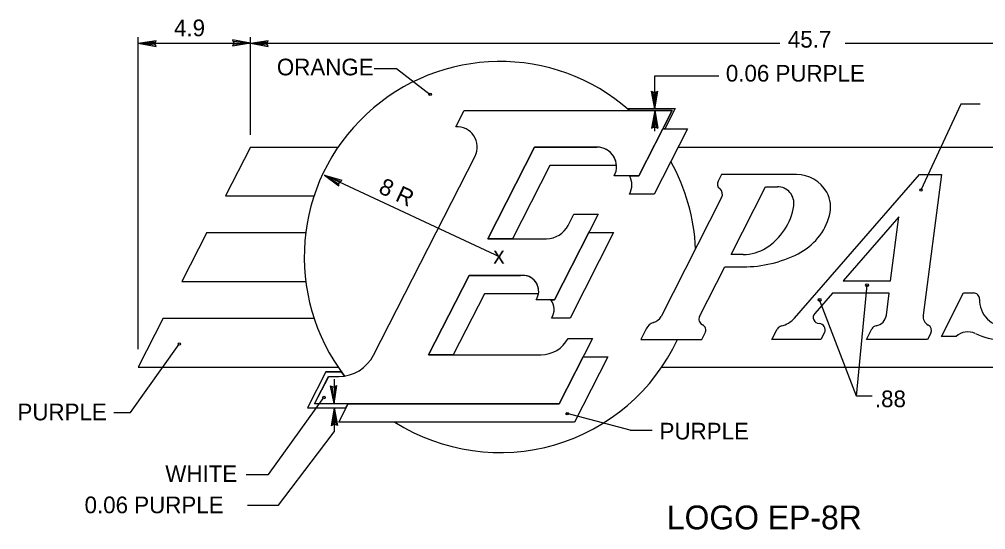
# Model space of a CAD drawing. Extents: x 10268197 to 10269179, y 2141503 to 2142677.
# Drawn here: x 10268587.94 to 10268622.88, y 2142117.46 to 2142135.93 of the extents above; entities that cross this region are included whole.
import ezdxf

# ---------------------------------------------------------------- set-up
doc = ezdxf.new("R2010")
doc.units = 0
for name, color, linetype in [('1', 7, 'Continuous'), ('Default', 7, 'Continuous'), ('TextDetails', 7, 'Continuous')]:
    doc.layers.add(name, color=color, linetype=linetype)

msp = doc.modelspace()

# ---------------------------------------------------------------- linework, layer by layer
at = {"layer": '1'}
for p, q in [((10268592.239, 2142123.995), (10268592.239, 2142135.291)), ((10268592.239, 2142135.07), (10268615.441, 2142135.07)), ((10268596.293, 2142131.752), (10268596.293, 2142135.291)), ((10268617.796, 2142135.07), (10268636.996, 2142135.07)), ((10268600.771, 2142134.159), (10268601.571, 2142134.159)), ((10268601.571, 2142134.159), (10268602.792, 2142133.217)), ((10268610.92, 2142133.893), (10268613.227, 2142133.893)), ((10268610.92, 2142132.722), (10268610.92, 2142133.893)), ((10268610.92, 2142131.88), (10268610.92, 2142132.642)), ((10268621.981, 2142132.861), (10268620.541, 2142129.754)), ((10268622.684, 2142132.861), (10268621.981, 2142132.861)), ((10268605.319, 2142127.328), (10268598.966, 2142130.29)), ((10268618.205, 2142122.289), (10268618.591, 2142126.308)), ((10268618.205, 2142122.289), (10268616.876, 2142125.778)), ((10268591.961, 2142121.699), (10268593.719, 2142124.177)), ((10268599.318, 2142122.905), (10268599.318, 2142122.025)), ((10268596.943, 2142119.455), (10268598.95, 2142122.244)), ((10268618.777, 2142122.289), (10268618.205, 2142122.289)), ((10268599.318, 2142121.868), (10268599.318, 2142120.996)), ((10268591.348, 2142121.699), (10268591.961, 2142121.699)), ((10268610.021, 2142121.063), (10268607.749, 2142121.658)), ((10268598.717, 2142120.203), (10268599.318, 2142120.996)), ((10268610.021, 2142121.063), (10268610.822, 2142121.063)), ((10268597.313, 2142118.35), (10268598.717, 2142120.203)), ((10268596.142, 2142119.455), (10268596.943, 2142119.455)), ((10268596.189, 2142118.35), (10268597.313, 2142118.35))]:
    msp.add_line(p, q, dxfattribs=at)
for centre, radius in [((10268602.792, 2142133.216), 0.0442), ((10268620.541, 2142129.753), 0.0442), ((10268618.591, 2142126.308), 0.0518), ((10268616.876, 2142125.778), 0.0518), ((10268593.719, 2142124.177), 0.0442), ((10268598.95, 2142122.243), 0.0442), ((10268607.749, 2142121.657), 0.0442)]:
    msp.add_circle(centre, radius, dxfattribs=at)
at = {"layer": 'Default'}
for p, q in [((10268592.239, 2142135.07), (10268592.886, 2142135.173)), ((10268592.239, 2142135.07), (10268592.859, 2142135.113)), ((10268592.239, 2142135.07), (10268592.882, 2142134.945)), ((10268592.239, 2142135.07), (10268592.857, 2142135.005)), ((10268592.834, 2142135.06), (10268592.886, 2142135.173)), ((10268592.882, 2142134.945), (10268592.834, 2142135.06)), ((10268595.697, 2142135.08), (10268595.646, 2142134.967)), ((10268596.293, 2142135.07), (10268595.646, 2142134.967)), ((10268596.293, 2142135.07), (10268595.65, 2142135.195)), ((10268595.65, 2142135.195), (10268595.697, 2142135.08)), ((10268596.293, 2142135.07), (10268595.674, 2142135.027)), ((10268596.293, 2142135.07), (10268595.675, 2142135.135)), ((10268596.293, 2142135.07), (10268596.94, 2142135.173)), ((10268596.293, 2142135.07), (10268596.912, 2142135.113)), ((10268596.293, 2142135.07), (10268596.936, 2142134.945)), ((10268596.293, 2142135.07), (10268596.911, 2142135.005)), ((10268596.888, 2142135.06), (10268596.94, 2142135.173)), ((10268596.936, 2142134.945), (10268596.888, 2142135.06)), ((10268610.921, 2142132.691), (10268610.796, 2142133.334)), ((10268610.796, 2142133.334), (10268610.911, 2142133.287)), ((10268610.921, 2142132.691), (10268610.856, 2142133.309)), ((10268610.911, 2142133.287), (10268611.024, 2142133.338)), ((10268610.921, 2142132.691), (10268611.024, 2142133.338)), ((10268610.921, 2142132.691), (10268610.965, 2142133.311)), ((10268603.718, 2142132.043), (10268604.019, 2142132.637)), ((10268604.019, 2142132.637), (10268611.54, 2142132.637)), ((10268609.924, 2142132.703), (10268611.649, 2142132.703)), ((10268611.54, 2142132.637), (10268610.336, 2142130.271)), ((10268610.921, 2142132.638), (10268610.796, 2142131.995)), ((10268610.921, 2142132.638), (10268610.856, 2142132.02)), ((10268610.921, 2142132.638), (10268611.024, 2142131.992)), ((10268610.921, 2142132.638), (10268610.965, 2142132.019)), ((10268611.649, 2142132.703), (10268611.277, 2142131.973)), ((10268610.334, 2142130.269), (10268611.203, 2142131.973)), ((10268610.334, 2142130.269), (10268611.203, 2142131.973)), ((10268610.796, 2142131.995), (10268610.911, 2142132.043)), ((10268612.097, 2142131.973), (10268610.891, 2142129.608)), ((10268612.097, 2142131.973), (10268610.891, 2142129.608)), ((10268610.911, 2142132.043), (10268611.024, 2142131.992)), ((10268611.203, 2142131.973), (10268612.097, 2142131.973)), ((10268611.203, 2142131.973), (10268612.097, 2142131.973)), ((10268596.293, 2142131.31), (10268595.392, 2142129.54)), ((10268596.293, 2142131.31), (10268599.466, 2142131.31)), ((10268606.568, 2142131.31), (10268604.878, 2142127.992)), ((10268604.878, 2142127.992), (10268606.568, 2142131.31)), ((10268604.878, 2142127.992), (10268606.568, 2142131.31)), ((10268608.823, 2142131.31), (10268606.568, 2142131.31)), ((10268606.568, 2142131.31), (10268608.823, 2142131.31)), ((10268606.568, 2142131.31), (10268608.823, 2142131.31)), ((10268611.758, 2142131.31), (10268636.996, 2142131.31)), ((10268600.745, 2142123.777), (10268604.417, 2142130.984)), ((10268607.124, 2142130.646), (10268605.771, 2142127.992)), ((10268607.124, 2142130.646), (10268605.771, 2142127.992)), ((10268609.531, 2142130.646), (10268607.124, 2142130.646)), ((10268609.531, 2142130.646), (10268607.124, 2142130.646)), ((10268598.966, 2142130.29), (10268599.595, 2142130.11)), ((10268598.966, 2142130.29), (10268599.496, 2142129.906)), ((10268598.966, 2142130.29), (10268599.498, 2142129.97)), ((10268598.966, 2142130.29), (10268599.545, 2142130.068)), ((10268610.336, 2142130.271), (10268609.45, 2142130.271)), ((10268610.005, 2142130.269), (10268610.334, 2142130.269)), ((10268610.005, 2142130.269), (10268610.334, 2142130.269)), ((10268613.326, 2142130.314), (10268613.206, 2142130.078)), ((10268616.036, 2142130.314), (10268613.326, 2142130.314)), ((10268615.968, 2142125.118), (10268620.486, 2142130.314)), ((10268620.486, 2142130.314), (10268621.282, 2142130.314)), ((10268621.282, 2142130.314), (10268620.62, 2142125.223)), ((10268599.496, 2142129.906), (10268599.501, 2142130.029)), ((10268599.501, 2142130.029), (10268599.595, 2142130.11)), ((10268613.673, 2142127.416), (10268614.925, 2142129.871)), ((10268614.925, 2142129.871), (10268615.352, 2142129.871)), ((10268595.392, 2142129.54), (10268598.594, 2142129.54)), ((10268610.891, 2142129.608), (10268610.006, 2142129.608)), ((10268610.891, 2142129.608), (10268610.006, 2142129.608)), ((10268613.334, 2142129.478), (10268611.143, 2142125.179)), ((10268608.872, 2142128.876), (10268607.295, 2142125.779)), ((10268607.783, 2142128.474), (10268607.988, 2142128.876)), ((10268607.988, 2142128.876), (10268608.872, 2142128.876)), ((10268619.745, 2142128.788), (10268617.725, 2142126.465)), ((10268619.443, 2142126.465), (10268619.745, 2142128.788)), ((10268594.717, 2142128.213), (10268593.816, 2142126.443)), ((10268594.717, 2142128.213), (10268598.295, 2142128.213)), ((10268607.295, 2142125.779), (10268608.535, 2142128.213)), ((10268607.295, 2142125.779), (10268608.535, 2142128.213)), ((10268609.428, 2142128.213), (10268607.85, 2142125.116)), ((10268609.428, 2142128.213), (10268607.85, 2142125.116)), ((10268608.535, 2142128.213), (10268609.428, 2142128.213)), ((10268608.535, 2142128.213), (10268609.428, 2142128.213)), ((10268604.878, 2142127.992), (10268606.995, 2142127.992)), ((10268605.771, 2142127.992), (10268604.878, 2142127.992)), ((10268605.771, 2142127.992), (10268604.878, 2142127.992)), ((10268614.112, 2142127.416), (10268613.673, 2142127.416)), ((10268604.202, 2142126.664), (10268602.736, 2142123.788)), ((10268602.736, 2142123.788), (10268604.202, 2142126.664)), ((10268602.736, 2142123.788), (10268604.202, 2142126.664)), ((10268606.143, 2142126.664), (10268604.202, 2142126.664)), ((10268604.202, 2142126.664), (10268606.06, 2142126.658)), ((10268604.202, 2142126.664), (10268606.06, 2142126.658)), ((10268612.533, 2142125.179), (10268613.448, 2142126.974)), ((10268613.448, 2142126.974), (10268614.112, 2142126.974)), ((10268593.816, 2142126.443), (10268598.295, 2142126.443)), ((10268617.725, 2142126.465), (10268619.443, 2142126.465)), ((10268604.757, 2142125.999), (10268603.63, 2142123.788)), ((10268604.757, 2142125.999), (10268603.63, 2142123.788)), ((10268606.71, 2142125.993), (10268604.757, 2142125.999)), ((10268606.71, 2142125.993), (10268604.757, 2142125.999)), ((10268617.342, 2142126.022), (10268616.7, 2142125.285)), ((10268619.398, 2142126.022), (10268617.342, 2142126.022)), ((10268619.292, 2142125.223), (10268619.398, 2142126.022)), ((10268621.279, 2142124.452), (10268622.082, 2142126.029)), ((10268622.082, 2142126.029), (10268622.438, 2142126.029)), ((10268607.295, 2142125.779), (10268606.628, 2142125.779)), ((10268607.156, 2142125.779), (10268607.295, 2142125.779)), ((10268607.156, 2142125.779), (10268607.295, 2142125.779)), ((10268593.14, 2142125.116), (10268592.239, 2142123.346)), ((10268593.14, 2142125.116), (10268598.594, 2142125.116)), ((10268607.85, 2142125.116), (10268607.187, 2142125.116)), ((10268607.85, 2142125.116), (10268607.187, 2142125.116)), ((10268610.605, 2142124.732), (10268610.407, 2142124.341)), ((10268612.619, 2142124.341), (10268612.739, 2142124.578)), ((10268615.154, 2142124.341), (10268615.346, 2142124.72)), ((10268617.054, 2142124.597), (10268616.924, 2142124.341)), ((10268618.568, 2142124.341), (10268618.764, 2142124.725)), ((10268620.897, 2142124.569), (10268620.78, 2142124.341)), ((10268608.663, 2142124.384), (10268607.458, 2142122.019)), ((10268607.778, 2142124.384), (10268608.663, 2142124.384)), ((10268610.407, 2142124.341), (10268612.619, 2142124.341)), ((10268616.924, 2142124.341), (10268615.154, 2142124.341)), ((10268620.78, 2142124.341), (10268618.568, 2142124.341)), ((10268621.817, 2142124.452), (10268621.279, 2142124.452)), ((10268602.736, 2142123.788), (10268606.797, 2142123.788)), ((10268603.63, 2142123.788), (10268602.736, 2142123.788)), ((10268603.63, 2142123.788), (10268602.736, 2142123.788)), ((10268607.458, 2142122.019), (10268608.325, 2142123.72)), ((10268607.458, 2142122.019), (10268608.325, 2142123.72)), ((10268609.219, 2142123.72), (10268608.013, 2142121.355)), ((10268609.219, 2142123.72), (10268608.013, 2142121.355)), ((10268608.325, 2142123.72), (10268609.219, 2142123.72)), ((10268608.325, 2142123.72), (10268609.219, 2142123.72)), ((10268592.239, 2142123.346), (10268599.466, 2142123.346)), ((10268599.019, 2142123.177), (10268598.354, 2142121.868)), ((10268599.019, 2142123.177), (10268599.584, 2142123.177)), ((10268611.171, 2142123.346), (10268632.938, 2142123.346)), ((10268598.61, 2142122.019), (10268599.112, 2142123.004)), ((10268599.112, 2142123.004), (10268599.483, 2142123.004)), ((10268599.318, 2142122.025), (10268599.192, 2142122.668)), ((10268599.192, 2142122.668), (10268599.307, 2142122.621)), ((10268599.318, 2142122.025), (10268599.253, 2142122.643)), ((10268599.307, 2142122.621), (10268599.42, 2142122.672)), ((10268599.318, 2142122.025), (10268599.42, 2142122.672)), ((10268599.318, 2142122.025), (10268599.361, 2142122.645)), ((10268598.354, 2142121.868), (10268599.741, 2142121.868)), ((10268607.458, 2142122.019), (10268598.61, 2142122.019)), ((10268599.318, 2142121.868), (10268599.215, 2142121.221)), ((10268599.318, 2142121.868), (10268599.274, 2142121.249)), ((10268599.318, 2142121.868), (10268599.442, 2142121.225)), ((10268599.318, 2142121.868), (10268599.382, 2142121.249)), ((10268599.495, 2142121.355), (10268599.832, 2142122.019)), ((10268599.495, 2142121.355), (10268599.832, 2142122.019)), ((10268599.832, 2142122.019), (10268607.458, 2142122.019)), ((10268599.832, 2142122.019), (10268607.458, 2142122.019)), ((10268599.327, 2142121.273), (10268599.215, 2142121.221)), ((10268599.442, 2142121.225), (10268599.327, 2142121.273)), ((10268608.013, 2142121.355), (10268599.495, 2142121.355)), ((10268608.013, 2142121.355), (10268599.495, 2142121.355))]:
    msp.add_line(p, q, dxfattribs=at)
for points in [[(10268609.924, 2142132.703), (10268611.649, 2142132.703), (10268611.277, 2142131.973), (10268611.203, 2142131.973), (10268611.54, 2142132.637), (10268610, 2142132.636)], [(10268599.584, 2142123.177), (10268599.019, 2142123.177), (10268598.354, 2142121.868), (10268599.741, 2142121.868), (10268599.832, 2142122.019), (10268598.61, 2142122.019), (10268599.125, 2142123.004), (10268599.488, 2142123.004), (10268599.7, 2142123.02)]]:
    msp.add_lwpolyline(points, close=True, dxfattribs=at)
for centre, radius, start, end in [((10268605.318, 2142127.327), 7.079, 48.5904, 217.4727), ((10268603.766, 2142131.315), 0.73, 332.9998, 93.8045), ((10268608.824, 2142130.601), 0.708, 332.2089, 90), ((10268608.824, 2142130.601), 0.708, 3.5833, 90), ((10268608.824, 2142130.601), 0.708, 3.5833, 90), ((10268605.318, 2142127.327), 7.079, 2.4236, 29.2771), ((10268609.379, 2142129.937), 0.708, 332.2089, 27.9127), ((10268609.379, 2142129.937), 0.708, 332.2089, 27.9127), ((10268616.036, 2142129.052), 1.261, 29.4315, 90), ((10268613.402, 2142129.977), 0.221, 152.9784, 231.1602), ((10268615.351, 2142129.274), 0.597, 351.076, 90), ((10268613.097, 2142129.598), 0.265, 333.0027, 51.1602), ((10268616.17, 2142129.128), 1.106, 344.7074, 29.4315), ((10268613.756, 2142129.524), 2.212, 302.4206, 351.076), ((10268615.104, 2142129.42), 2.212, 296.6431, 344.7074), ((10268606.994, 2142128.876), 0.885, 270, 332.9883), ((10268614.112, 2142128.964), 1.548, 270, 302.4206), ((10268614.112, 2142131.397), 4.424, 270, 296.6431), ((10268606.143, 2142126.088), 0.575, 350.3502, 98.3344), ((10268606.143, 2142126.088), 0.575, 350.3502, 98.3344), ((10268606.143, 2142126.088), 0.575, 327.421, 90), ((10268622.438, 2142125.807), 0.221, 358.6664, 90), ((10268606.702, 2142125.425), 0.575, 327.421, 37.9799), ((10268606.702, 2142125.425), 0.575, 327.421, 37.9799), ((10268623.654, 2142125.779), 0.995, 178.6665, 270), ((10268616.867, 2142125.139), 0.221, 138.9824, 268.6869), ((10268610.999, 2142124.53), 0.442, 106.4317, 152.9742), ((10268610.749, 2142125.379), 0.442, 286.4317, 332.9959), ((10268612.73, 2142125.078), 0.221, 152.9884, 244.7832), ((10268615.3, 2142125.698), 0.885, 282.7162, 318.9966), ((10268616.857, 2142124.697), 0.221, 332.9784, 88.6869), ((10268618.854, 2142125.279), 0.442, 279.2397, 352.5632), ((10268620.971, 2142125.176), 0.354, 172.5884, 241.8673), ((10268612.542, 2142124.677), 0.221, 333.0239, 64.7832), ((10268615.544, 2142124.619), 0.221, 102.7162, 153.0239), ((10268618.961, 2142124.624), 0.221, 99.2397, 153.0239), ((10268620.699, 2142124.669), 0.221, 332.9784, 61.8673), ((10268622.24, 2142124), 0.619, 64.3795, 133.1892), ((10268605.318, 2142127.327), 7.079, 237.5383, 335.047), ((10268606.797, 2142124.894), 1.106, 270, 332.5096), ((10268623.465, 2142126.553), 2.212, 244.3795, 270), ((10268599.483, 2142124.419), 1.416, 270, 332.9991)]:
    msp.add_arc(centre, radius, start, end, dxfattribs=at)

# ---------------------------------------------------------------- texts
at = {"layer": '1'}
for s, height, p in [('4.9', 0.6037, (10268593.53, 2142135.322)), ('45.7', 0.6037, (10268615.728, 2142134.909)), ('ORANGE', 0.6037, (10268597.249, 2142133.905)), ('0.06 PURPLE', 0.60368, (10268613.487, 2142133.679)), ('x', 0.604, (10268605.078, 2142127.092)), ('.88', 0.6037, (10268618.876, 2142121.892)), ('PURPLE', 0.6037, (10268587.869, 2142121.416)), ('PURPLE', 0.6037, (10268611.089, 2142120.722)), ('WHITE', 0.6037, (10268593.214, 2142119.183)), ('0.06 PURPLE', 0.60368, (10268590.296, 2142118.052))]:
    msp.add_text(s, height=height, dxfattribs=at).set_placement(p)
msp.add_text('8 R', height=0.6037, rotation=334.9991, dxfattribs=at).set_placement((10268600.887, 2142129.668))
at = {"layer": 'TextDetails'}
msp.add_text('LOGO EP-8R', height=0.8624, dxfattribs=at).set_placement((10268611.352, 2142117.469))

doc.saveas('drawing.dxf')
